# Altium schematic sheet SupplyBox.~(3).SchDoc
size B; SheetNumber: 1; SheetTotal: 1
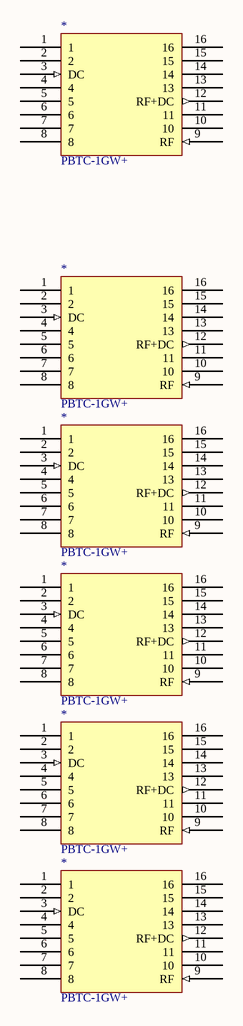
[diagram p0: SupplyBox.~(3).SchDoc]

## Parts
(Parts that share a designator on the sheet are numbered #1, #2 ... from top to bottom, then left to right.)
*#1  PBTC-1GW+  [PBTC-1GW+]
*#2  PBTC-1GW+  [PBTC-1GW+]
*#3  PBTC-1GW+  [PBTC-1GW+]
*#4  PBTC-1GW+  [PBTC-1GW+]
*#5  PBTC-1GW+  [PBTC-1GW+]
*#6  PBTC-1GW+  [PBTC-1GW+]

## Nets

Not connected (* = marked no-connect by the designer): *#1 1 2 3(DC) 4 5 6 7 8 9(RF) 10 11 12(RF+DC) 13 14 15 16; *#2 1 2 3(DC) 4 5 6 7 8 9(RF) 10 11 12(RF+DC) 13 14 15 16; *#3 1 2 3(DC) 4 5 6 7 8 9(RF) 10 11 12(RF+DC) 13 14 15 16; *#4 1 2 3(DC) 4 5 6 7 8 9(RF) 10 11 12(RF+DC) 13 14 15 16; *#5 1 2 3(DC) 4 5 6 7 8 9(RF) 10 11 12(RF+DC) 13 14 15 16; *#6 1 2 3(DC) 4 5 6 7 8 9(RF) 10 11 12(RF+DC) 13 14 15 16

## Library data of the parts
*#1-*#6 = CMP-00025-00003-1: Monitor TEE DC Block, 0.1MHz Min, 1000MHz Max, 1dB Insertion Loss-Max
